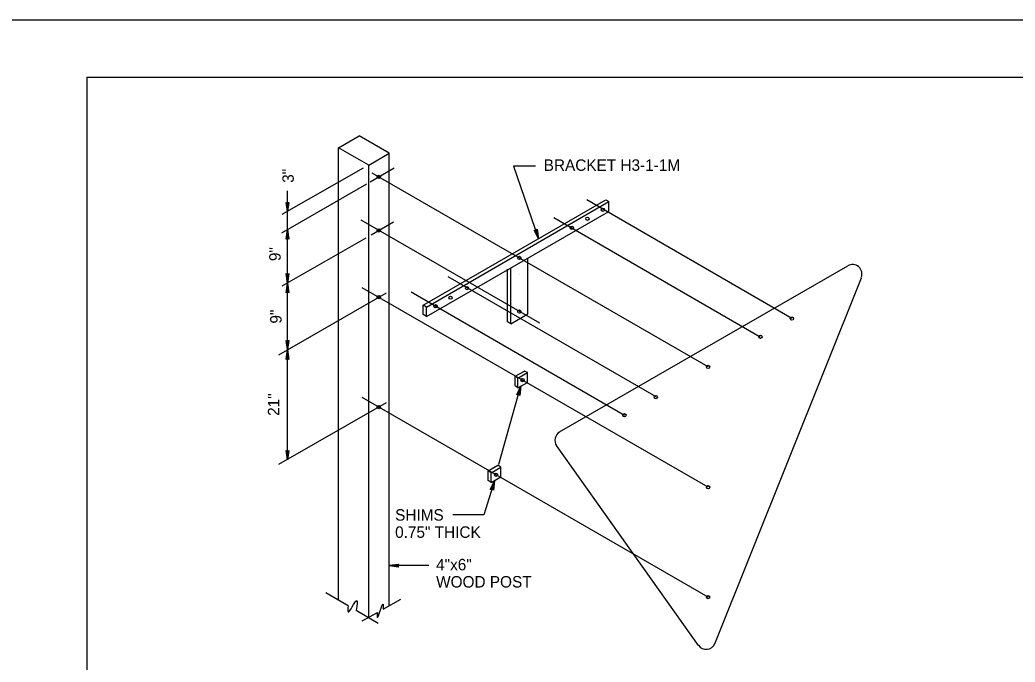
# Model space of a CAD drawing. Extents: x 648590 to 650336, y 294467 to 295061.
# Drawn here: x 649453.6 to 649713.9, y 294893.5 to 295061.4 of the extents above; entities that cross this region are included whole.
import ezdxf

# ---------------------------------------------------------------- set-up
doc = ezdxf.new("R2010")
doc.units = 0
for name, color, linetype in [('1', 7, 'Continuous'), ('2', 7, 'Continuous'), ('3', 7, 'Continuous'), ('PLT-BNDY', 7, 'Continuous')]:
    doc.layers.add(name, color=color, linetype=linetype)

msp = doc.modelspace()

# ---------------------------------------------------------------- linework, layer by layer
at = {"layer": '1'}
for q in [(650257.1, 295046.45), (649471.1, 294482.45)]:
    msp.add_line((649471.1, 295046.45), q, dxfattribs=at)
at = {"layer": '2'}
for points in [[(649588.47, 295023.21), (649582.72, 295023.21), (649589.22, 295004.21)], [(649588.72, 295006.59), (649588.6, 295006.34), (649589.22, 295004.21), (649588.72, 295006.59), (649588.85, 295006.71), (649589.22, 295004.21), (649588.35, 295006.34), (649588.22, 295006.34), (649589.22, 295004.21), (649588.1, 295006.46), (649588.22, 295006.34)], [(649583.72, 294963.46), (649583.97, 294963.46), (649584.6, 294965.71), (649583.72, 294963.46), (649583.6, 294963.34), (649584.6, 294965.71), (649584.1, 294963.46), (649584.22, 294963.34), (649584.6, 294965.71), (649584.35, 294963.21), (649584.22, 294963.34)], [(649576.72, 294938.71), (649576.97, 294938.71), (649577.72, 294940.84), (649576.72, 294938.71), (649576.6, 294938.59), (649577.72, 294940.84), (649577.22, 294938.71), (649577.35, 294938.59), (649577.72, 294940.84), (649577.47, 294938.46), (649577.35, 294938.59)], [(649552.6, 294918.34), (649552.47, 294918.59), (649550.22, 294918.71), (649552.6, 294918.34), (649552.72, 294918.34), (649550.22, 294918.71), (649552.47, 294918.84), (649552.6, 294918.96), (649550.22, 294918.71), (649552.72, 294919.09), (649552.6, 294918.96)], [(649560.6, 294918.71), (649550.22, 294918.71)]]:
    msp.add_lwpolyline(points, dxfattribs=at)
for centre, start, end in [((649671.33, 294994.97), 338.2171, 119.9923), ((649596, 294951.48), 119.9878, 215.3941), ((649633.09, 294899.29), 215.3991, 336.1301)]:
    msp.add_arc(centre, 2.49, start, end, dxfattribs=at)
at = {"layer": '3'}
for p, q in [((649536.97, 295027.96), (649542.35, 295031.09)), ((649550.22, 295026.59), (649542.35, 295031.09)), ((649536.97, 294909.59), (649536.97, 295027.96)), ((649544.85, 295023.46), (649536.97, 295027.96)), ((649544.85, 295023.46), (649550.22, 295026.59)), ((649550.22, 294908.34), (649550.22, 295026.59)), ((649544.85, 294905.21), (649544.85, 295023.46)), ((649522.22, 295010.59), (649543.47, 295022.71)), ((649545.22, 295019.09), (649551.47, 295022.71)), ((649633.6, 294970.71), (649545.72, 295021.34)), ((649547.47, 295020.34), (649547.47, 295020.34)), ((649522.1, 295005.71), (649544.35, 295018.59)), ((649523.6, 295006.58), (649523.6, 295016.75)), ((649559.1, 294986.84), (649606.85, 295014.34)), ((649559.97, 294986.34), (649607.6, 295013.96)), ((649655.47, 294983.34), (649601.85, 295014.34)), ((649605.47, 295013.84), (649605.47, 295013.84)), ((649606.85, 295014.34), (649607.6, 295013.96)), ((649607.6, 295011.34), (649607.6, 295013.96)), ((649559.97, 294983.84), (649607.6, 295011.34)), ((649607.6, 295011.34), (649607.6, 295011.34)), ((649589.6, 294982.09), (649542.85, 295009.09)), ((649545.47, 295005.21), (649551.35, 295008.59)), ((649647.22, 294978.46), (649593.22, 295009.71)), ((649523.6, 294992.59), (649523.6, 295006.59)), ((649547.47, 295006.34), (649547.47, 295006.34)), ((649522.22, 294991.84), (649544.22, 295004.46)), ((649583.22, 294999.71), (649583.22, 294999.71)), ((649578.97, 294997.46), (649578.97, 294997.46)), ((649580.47, 294998.21), (649580.47, 294998.21)), ((649581.72, 294999.09), (649581.72, 294999.09)), ((649586.47, 294984.59), (649586.47, 294999.21)), ((649594.72, 294953.71), (649670.1, 294997.09)), ((649574.97, 294995.09), (649574.97, 294995.09)), ((649576.35, 294995.84), (649576.35, 294995.84)), ((649577.72, 294996.59), (649577.72, 294996.59)), ((649581.1, 294982.46), (649581.1, 294996.21)), ((649581.97, 294981.96), (649581.97, 294996.59)), ((649584.22, 294994.96), (649584.22, 294994.96)), ((649523.6, 294975.21), (649523.6, 294992.59)), ((649619.97, 294962.84), (649565.6, 294994.21)), ((649569.47, 294991.96), (649569.47, 294991.96)), ((649570.85, 294992.71), (649570.85, 294992.71)), ((649572.1, 294993.46), (649572.1, 294993.46)), ((649573.6, 294994.21), (649573.6, 294994.21)), ((649635.35, 294898.21), (649673.72, 294993.96)), ((649521.35, 294973.84), (649549.47, 294990.09)), ((649633.6, 294939.21), (649543.1, 294991.34)), ((649611.72, 294957.96), (649555.97, 294990.21)), ((649565.35, 294989.59), (649565.35, 294989.59)), ((649566.72, 294990.34), (649566.72, 294990.34)), ((649568.1, 294991.09), (649568.1, 294991.09)), ((649559.97, 294986.34), (649559.1, 294986.84)), ((649559.1, 294984.34), (649559.1, 294986.84)), ((649561.22, 294987.21), (649561.22, 294987.21)), ((649562.72, 294987.96), (649562.72, 294987.96)), ((649563.97, 294988.71), (649563.97, 294988.71)), ((649566.22, 294988.84), (649566.22, 294988.84)), ((649559.97, 294983.84), (649559.1, 294984.34)), ((649559.97, 294983.84), (649559.97, 294986.34)), ((649559.97, 294986.34), (649559.97, 294986.34)), ((649581.97, 294981.96), (649586.47, 294984.59)), ((649584.22, 294985.09), (649584.22, 294985.09)), ((649581.97, 294981.96), (649581.1, 294982.46)), ((649523.6, 294946.34), (649523.6, 294973.84)), ((649583.1, 294968.21), (649585.6, 294969.59)), ((649583.85, 294967.71), (649583.1, 294968.21)), ((649583.1, 294965.71), (649583.1, 294968.21)), ((649583.85, 294967.71), (649586.35, 294969.21)), ((649586.35, 294969.21), (649585.6, 294969.59)), ((649586.35, 294966.59), (649586.35, 294969.21)), ((649583.85, 294965.21), (649583.1, 294965.71)), ((649583.85, 294965.21), (649583.85, 294967.71)), ((649583.85, 294965.21), (649586.35, 294966.59)), ((649521.35, 294945.21), (649549.47, 294961.34)), ((649633.6, 294910.46), (649543.1, 294962.71)), ((649631.1, 294897.84), (649593.97, 294950.09)), ((649576.1, 294943.46), (649578.6, 294944.96)), ((649579.35, 294944.46), (649578.6, 294944.96)), ((649576.85, 294942.96), (649576.1, 294943.46)), ((649576.1, 294940.96), (649576.1, 294943.46)), ((649576.85, 294942.96), (649579.35, 294944.46)), ((649576.85, 294940.46), (649576.85, 294942.96)), ((649579.35, 294941.96), (649579.35, 294944.46)), ((649577.72, 294940.84), (649574.96, 294931.98)), ((649576.85, 294940.46), (649576.1, 294940.96)), ((649576.85, 294940.46), (649579.35, 294941.96)), ((649574.96, 294931.98), (649566.86, 294931.98)), ((649539.47, 294908.21), (649533.6, 294911.59)), ((649548.6, 294907.34), (649553.22, 294909.96)), ((649547.35, 294903.59), (649541.6, 294906.96)), ((649543.1, 294904.21), (649547.1, 294906.46))]:
    msp.add_line(p, q, dxfattribs=at)
for points in [[(649523.97, 295013.59), (649523.72, 295013.59), (649523.6, 295011.34), (649523.97, 295013.59), (649523.97, 295013.71), (649523.6, 295011.34), (649523.47, 295013.59), (649523.35, 295013.59), (649523.6, 295011.34), (649523.22, 295013.71), (649523.35, 295013.59)], [(649523.35, 295004.21), (649523.47, 295004.34), (649523.6, 295006.59), (649523.35, 295004.21), (649523.22, 295004.09), (649523.6, 295006.59), (649523.72, 295004.34), (649523.85, 295004.21), (649523.6, 295006.59), (649523.97, 295004.09), (649523.85, 295004.21)], [(649523.97, 294994.96), (649523.72, 294994.84), (649523.6, 294992.59), (649523.97, 294994.96), (649523.97, 294995.09), (649523.6, 294992.59), (649523.47, 294994.84), (649523.35, 294994.96), (649523.6, 294992.59), (649523.22, 294995.09), (649523.35, 294994.96)], [(649523.35, 294990.21), (649523.47, 294990.34), (649523.6, 294992.59), (649523.35, 294990.21), (649523.22, 294990.09), (649523.6, 294992.59), (649523.72, 294990.34), (649523.85, 294990.21), (649523.6, 294992.59), (649523.97, 294990.09), (649523.85, 294990.21)], [(649523.97, 294977.46), (649523.72, 294977.46), (649523.6, 294975.21), (649523.97, 294977.46), (649523.97, 294977.59), (649523.6, 294975.21), (649523.47, 294977.46), (649523.35, 294977.46), (649523.6, 294975.21), (649523.22, 294977.59), (649523.35, 294977.46)], [(649523.35, 294972.71), (649523.47, 294972.84), (649523.6, 294975.21), (649523.35, 294972.71), (649523.22, 294972.59), (649523.6, 294975.21), (649523.72, 294972.84), (649523.85, 294972.71), (649523.6, 294975.21), (649523.97, 294972.59), (649523.85, 294972.71)], [(649578.85, 294945.21), (649584.6, 294965.71)], [(649523.97, 294948.71), (649523.72, 294948.59), (649523.6, 294946.34), (649523.97, 294948.71), (649523.97, 294948.84), (649523.6, 294946.34), (649523.47, 294948.59), (649523.35, 294948.71), (649523.6, 294946.34), (649523.22, 294948.84), (649523.35, 294948.71)]]:
    msp.add_lwpolyline(points, dxfattribs=at)
for centre in [(649547.48, 295020.39), (649602.03, 295009.44), (649606.09, 295011.79), (649597.92, 295007.07), (649547.48, 295006.38), (649584.23, 294999.17), (649570.54, 294991.27), (649547.48, 294988.92), (649566.23, 294988.78), (649562.33, 294986.53), (649584.23, 294985.16), (649655.48, 294983.31), (649647.28, 294978.57), (649633.59, 294970.67), (649585.08, 294967.22), (649619.9, 294962.77), (649547.48, 294960.16), (649611.69, 294958.03), (649578.12, 294942.47), (649633.59, 294939.21), (649633.59, 294910.44)]:
    msp.add_circle(centre, 0.428, dxfattribs=at)
for points in [[(649539.47, 294908.21), (649539.47, 294906.59), (649541.72, 294909.59), (649541.6, 294906.96)], [(649547.1, 294906.46), (649547.1, 294905.09), (649548.6, 294908.59), (649548.6, 294907.34)]]:
    msp.add_spline(points, degree=3, dxfattribs=at)
at = {"layer": 'PLT-BNDY'}
msp.add_lwpolyline([(649431.1, 295061.45), (650272.1, 295061.45), (650272.1, 294467.45), (649431.1, 294467.45)], close=True, dxfattribs=at)

# ---------------------------------------------------------------- texts
at = {"layer": '3'}
for s, p in [('BRACKET H3-1-1M', (649590.6, 295021.96)), ('SHIMS', (649551.75, 294930.46)), ('0.75" THICK', (649551.75, 294925.96)), ('4"x6"', (649562.47, 294917.46)), ('WOOD POST', (649562.47, 294912.96))]:
    msp.add_text(s, height=3, dxfattribs=at).set_placement(p)
for s, p in [('3"', (649525.26, 295018.83)), ('9"', (649521.83, 294998.35)), ('9"', (649522.07, 294982)), ('21"', (649521.47, 294957.86))]:
    msp.add_text(s, height=3, rotation=90, dxfattribs=at).set_placement(p)

doc.saveas('drawing.dxf')
